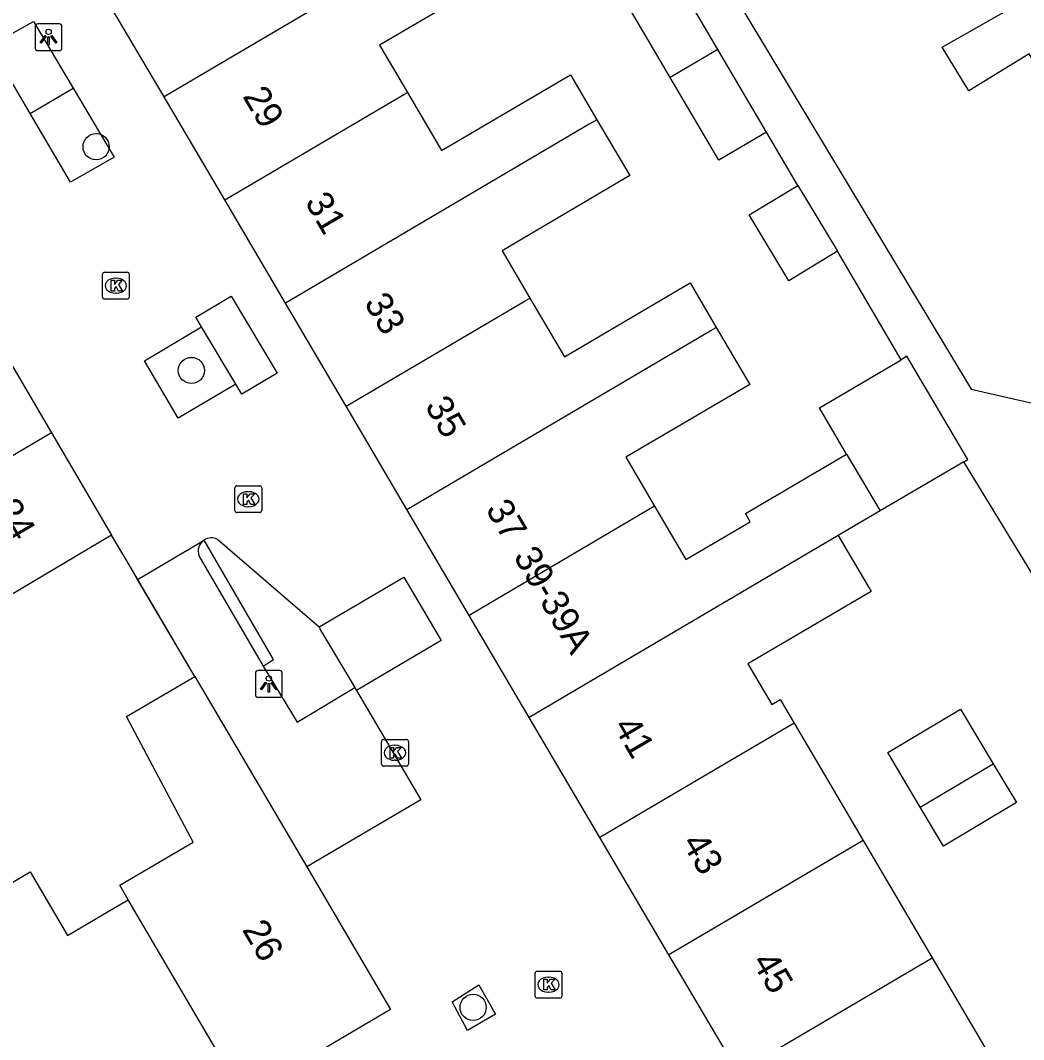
# Model space of a CAD drawing. Extents: x 161771 to 163125, y 382479 to 383177.
# Drawn here: x 162197.24 to 162234.66, y 382820.33 to 382858.34 of the extents above; entities that cross this region are included whole.
import ezdxf

# ---------------------------------------------------------------- set-up
doc = ezdxf.new("R2010")
doc.units = 0
for name, color, linetype in [('IMGEO_Boom', 7, 'Continuous'), ('IMGEO_Groenvoorziening', 7, 'Continuous'), ('IMGEO_Kolk', 7, 'Continuous'), ('IMGEO_Lichtpunt', 7, 'Continuous'), ('IMGEO_Muur', 7, 'Continuous'), ('IMGEO_Pand', 7, 'Continuous'), ('IMGEO_Pand_nummerreeks', 7, 'Continuous'), ('IMGEO_Parkeervlak_open', 7, 'Continuous'), ('IMGEO_Voetpad_open', 7, 'Continuous'), ('IMGEO_Woonerf_open', 7, 'Continuous')]:
    doc.layers.add(name, color=color, linetype=linetype)

msp = doc.modelspace()

# ---------------------------------------------------------------- linework, layer by layer
at = {"layer": 'IMGEO_Boom'}
for centre in [(162200.067, 382853.624), (162203.62, 382845.282), (162214.13, 382821.532)]:
    msp.add_circle(centre, 0.489, dxfattribs=at)
at = {"layer": 'IMGEO_Groenvoorziening'}
msp.add_lwpolyline([(162197.603, 382854.86), (162199.207, 382855.812)], dxfattribs=at)
at = {"layer": 'IMGEO_Kolk'}
for p, q in [((162200.304, 382848.017), (162200.304, 382848.869)), ((162200.379, 382848.943), (162201.231, 382848.943)), ((162200.792, 382848.723), (162200.817, 382848.723)), ((162201.305, 382848.869), (162201.305, 382848.017)), ((162201.231, 382847.943), (162200.379, 382847.943)), ((162200.815, 382848.163), (162200.79, 382848.163)), ((162205.243, 382840.056), (162205.243, 382840.908)), ((162205.318, 382840.982), (162206.17, 382840.982)), ((162205.731, 382840.762), (162205.756, 382840.762)), ((162206.244, 382840.908), (162206.244, 382840.056)), ((162206.17, 382839.982), (162205.318, 382839.982)), ((162205.754, 382840.202), (162205.729, 382840.202)), ((162210.714, 382830.598), (162210.714, 382831.45)), ((162210.789, 382831.524), (162211.641, 382831.524)), ((162211.202, 382831.304), (162211.227, 382831.304)), ((162211.715, 382831.45), (162211.715, 382830.598)), ((162211.641, 382830.524), (162210.789, 382830.524)), ((162211.225, 382830.744), (162211.2, 382830.744)), ((162216.442, 382821.953), (162216.442, 382822.805)), ((162216.517, 382822.879), (162217.369, 382822.879)), ((162217.443, 382822.805), (162217.443, 382821.953)), ((162216.93, 382822.659), (162216.955, 382822.659)), ((162216.953, 382822.099), (162216.928, 382822.099)), ((162217.369, 382821.879), (162216.517, 382821.879))]:
    msp.add_line(p, q, dxfattribs=at)
for points in [[(162200.304, 382848.017), (162200.304, 382848.869)], [(162200.379, 382848.943), (162201.231, 382848.943)], [(162201.305, 382848.869), (162201.305, 382848.017)], [(162200.625, 382848.643), (162200.748, 382848.643), (162200.748, 382848.492), (162200.878, 382848.643), (162201.042, 382848.643), (162200.896, 382848.492), (162201.049, 382848.243), (162200.897, 382848.243), (162200.812, 382848.407), (162200.748, 382848.34), (162200.748, 382848.243), (162200.625, 382848.243), (162200.625, 382848.643)], [(162201.231, 382847.943), (162200.379, 382847.943)], [(162205.243, 382840.056), (162205.243, 382840.908)], [(162205.318, 382840.982), (162206.17, 382840.982)], [(162205.564, 382840.682), (162205.687, 382840.682), (162205.687, 382840.531), (162205.817, 382840.682), (162205.981, 382840.682), (162205.835, 382840.531), (162205.988, 382840.282), (162205.836, 382840.282), (162205.751, 382840.446), (162205.687, 382840.379), (162205.687, 382840.282), (162205.564, 382840.282), (162205.564, 382840.682)], [(162206.244, 382840.908), (162206.244, 382840.056)], [(162206.17, 382839.982), (162205.318, 382839.982)], [(162210.714, 382830.598), (162210.714, 382831.45)], [(162210.789, 382831.524), (162211.641, 382831.524)], [(162211.035, 382831.224), (162211.158, 382831.224), (162211.158, 382831.073), (162211.288, 382831.224), (162211.452, 382831.224), (162211.306, 382831.073), (162211.459, 382830.824), (162211.307, 382830.824), (162211.222, 382830.988), (162211.158, 382830.921), (162211.158, 382830.824), (162211.035, 382830.824), (162211.035, 382831.224)], [(162211.715, 382831.45), (162211.715, 382830.598)], [(162211.641, 382830.524), (162210.789, 382830.524)], [(162216.442, 382821.953), (162216.442, 382822.805)], [(162216.517, 382822.879), (162217.369, 382822.879)], [(162217.443, 382822.805), (162217.443, 382821.953)], [(162216.763, 382822.579), (162216.886, 382822.579), (162216.886, 382822.428), (162217.016, 382822.579), (162217.18, 382822.579), (162217.034, 382822.428), (162217.187, 382822.179), (162217.035, 382822.179), (162216.95, 382822.343), (162216.886, 382822.276), (162216.886, 382822.179), (162216.763, 382822.179), (162216.763, 382822.579)], [(162217.369, 382821.879), (162216.517, 382821.879)]]:
    msp.add_lwpolyline(points, dxfattribs=at)
for centre, start, end in [((162200.381, 382848.867), 91.552, 178.448), ((162200.381, 382848.867), 91.552, 178.448), ((162201.229, 382848.867), 1.552, 88.448), ((162201.229, 382848.867), 1.552, 88.448), ((162200.381, 382848.019), 181.552, 268.448), ((162200.381, 382848.019), 181.552, 268.448), ((162201.229, 382848.019), 271.552, 358.448), ((162201.229, 382848.019), 271.552, 358.448), ((162205.32, 382840.906), 91.552, 178.448), ((162205.32, 382840.906), 91.552, 178.448), ((162206.168, 382840.906), 1.552, 88.448), ((162206.168, 382840.906), 1.552, 88.448), ((162205.32, 382840.058), 181.552, 268.448), ((162205.32, 382840.058), 181.552, 268.448), ((162206.168, 382840.058), 271.552, 358.448), ((162206.168, 382840.058), 271.552, 358.448), ((162210.791, 382831.448), 91.552, 178.448), ((162210.791, 382831.448), 91.552, 178.448), ((162211.639, 382831.448), 1.552, 88.448), ((162211.639, 382831.448), 1.552, 88.448), ((162210.791, 382830.6), 181.552, 268.448), ((162210.791, 382830.6), 181.552, 268.448), ((162211.639, 382830.6), 271.552, 358.448), ((162211.639, 382830.6), 271.552, 358.448), ((162216.519, 382822.803), 91.552, 178.448), ((162216.519, 382822.803), 91.552, 178.448), ((162217.367, 382822.803), 1.552, 88.448), ((162217.367, 382822.803), 1.552, 88.448), ((162216.519, 382821.955), 181.552, 268.448), ((162216.519, 382821.955), 181.552, 268.448), ((162217.367, 382821.955), 271.552, 358.448), ((162217.367, 382821.955), 271.552, 358.448)]:
    msp.add_arc(centre, 0.0765, start, end, dxfattribs=at)
for centre, major_axis, ratio, start_param, end_param in [((162200.791, 382848.443), (-0.387, 0.002), 0.722429, 4.712389, 7.853982), ((162200.816, 382848.443), (-0.39, 0.002), 0.717154, 1.570796, 4.712389), ((162205.73, 382840.482), (-0.387, 0.002), 0.722429, 4.712389, 7.853982), ((162205.755, 382840.482), (-0.39, 0.002), 0.717154, 1.570796, 4.712389), ((162211.201, 382831.024), (-0.387, 0.002), 0.722429, 4.712389, 7.853982), ((162211.226, 382831.024), (-0.39, 0.002), 0.717154, 1.570796, 4.712389), ((162216.929, 382822.379), (-0.387, 0.002), 0.722429, 4.712389, 7.853982), ((162216.954, 382822.379), (-0.39, 0.002), 0.717154, 1.570796, 4.712389)]:
    msp.add_ellipse(centre, major_axis=major_axis, ratio=ratio, start_param=start_param, end_param=end_param, dxfattribs=at)
at = {"layer": 'IMGEO_Lichtpunt'}
for p, q in [((162198.698, 382858.207), (162197.89, 382858.207)), ((162198.698, 382858.207), (162197.89, 382858.207)), ((162197.796, 382858.112), (162197.796, 382857.305)), ((162197.796, 382858.112), (162197.796, 382857.305)), ((162198.792, 382857.305), (162198.792, 382858.112)), ((162198.792, 382857.305), (162198.792, 382858.112)), ((162197.89, 382857.211), (162198.698, 382857.211)), ((162197.89, 382857.211), (162198.698, 382857.211)), ((162206.011, 382833.997), (162206.011, 382833.19)), ((162206.011, 382833.997), (162206.011, 382833.19)), ((162206.913, 382834.092), (162206.105, 382834.092)), ((162206.913, 382834.092), (162206.105, 382834.092)), ((162207.007, 382833.19), (162207.007, 382833.997)), ((162207.007, 382833.19), (162207.007, 382833.997)), ((162206.105, 382833.096), (162206.913, 382833.096)), ((162206.105, 382833.096), (162206.913, 382833.096))]:
    msp.add_line(p, q, dxfattribs=at)
for points in [[(162198.17, 382857.776), (162198.209, 382857.748), (162198.021, 382857.486), (162197.983, 382857.513), (162198.17, 382857.776)], [(162198.382, 382857.748), (162198.42, 382857.775), (162198.607, 382857.513), (162198.568, 382857.485), (162198.382, 382857.748)], [(162198.272, 382857.728), (162198.319, 382857.728), (162198.319, 382857.406), (162198.272, 382857.406), (162198.272, 382857.728)], [(162206.385, 382833.661), (162206.424, 382833.633), (162206.236, 382833.371), (162206.198, 382833.398), (162206.385, 382833.661)], [(162206.487, 382833.613), (162206.534, 382833.613), (162206.534, 382833.291), (162206.487, 382833.291), (162206.487, 382833.613)], [(162206.597, 382833.633), (162206.635, 382833.66), (162206.822, 382833.398), (162206.783, 382833.37), (162206.597, 382833.633)]]:
    msp.add_lwpolyline(points, dxfattribs=at)
for centre in [(162198.295, 382857.91), (162206.51, 382833.795)]:
    msp.add_circle(centre, 0.0994, dxfattribs=at)
for centre, start, end in [((162197.89, 382858.112), 90, 180), ((162197.89, 382858.112), 90, 180), ((162198.698, 382858.112), 0, 90), ((162198.698, 382858.112), 0, 90), ((162197.89, 382857.305), 180, 270), ((162197.89, 382857.305), 180, 270), ((162198.698, 382857.305), 270, 0), ((162198.698, 382857.305), 270, 360), ((162206.105, 382833.997), 90, 180), ((162206.105, 382833.997), 90, 180), ((162206.913, 382833.997), 0, 90), ((162206.913, 382833.997), 0, 90), ((162206.105, 382833.19), 180, 270), ((162206.105, 382833.19), 180, 270), ((162206.913, 382833.19), 270, 0), ((162206.913, 382833.19), 270, 360)]:
    msp.add_arc(centre, 0.0946, start, end, dxfattribs=at)
at = {"layer": 'IMGEO_Muur'}
msp.add_lwpolyline([(162203.743, 382833.873), (162201.172, 382838.24)], dxfattribs=at)
at = {"layer": 'IMGEO_Pand'}
for points in [[(162237.48, 382857.838), (162235.233, 382856.474), (162234.864, 382857.089), (162232.625, 382855.706), (162231.624, 382857.338), (162233.93, 382858.644), (162231.966, 382861.913), (162229.224, 382866.48)], [(162214.218, 382862.326), (162213.938, 382862.161), (162202.6, 382855.486)], [(162214.218, 382862.326), (162215.445, 382860.238), (162210.639, 382857.413), (162211.676, 382855.649)], [(162221.48, 382856.206), (162219.735, 382859.174), (162221.515, 382860.221)], [(162223.26, 382857.253), (162221.515, 382860.221)], [(162202.6, 382855.486), (162200.335, 382859.333)], [(162223.26, 382857.253), (162221.48, 382856.206)], [(162225.075, 382854.166), (162223.26, 382857.253)], [(162211.676, 382855.649), (162212.953, 382853.478), (162217.762, 382856.305), (162218.747, 382854.63)], [(162225.075, 382854.166), (162223.295, 382853.12), (162221.48, 382856.206)], [(162204.864, 382851.639), (162211.543, 382855.571), (162211.676, 382855.649)], [(162204.864, 382851.639), (162202.6, 382855.486)], [(162218.747, 382854.63), (162218.461, 382854.462), (162207.129, 382847.791)], [(162218.747, 382854.63), (162219.971, 382852.547), (162215.21, 382849.748), (162216.249, 382847.98)], [(162227.722, 382849.728), (162225.901, 382848.63), (162224.421, 382851.086), (162226.242, 382852.183)], [(162226.242, 382852.183), (162227.722, 382849.728)], [(162207.129, 382847.791), (162204.864, 382851.639)], [(162216.249, 382847.98), (162217.535, 382845.793), (162222.22, 382848.547), (162223.195, 382846.888)], [(162209.393, 382843.944), (162216.069, 382847.874), (162216.249, 382847.98)], [(162209.393, 382843.944), (162207.129, 382847.791)], [(162196.128, 382846.817), (162198.399, 382842.955)], [(162211.658, 382840.097), (162222.976, 382846.759), (162223.195, 382846.888)], [(162223.195, 382846.888), (162224.445, 382844.761), (162219.824, 382842.045), (162220.899, 382840.216)], [(162228.06, 382842.164), (162227.044, 382843.892), (162230.09, 382845.683)], [(162232.428, 382841.879), (162232.576, 382841.966), (162230.312, 382845.814), (162230.09, 382845.683)], [(162211.658, 382840.097), (162209.393, 382843.944)], [(162198.399, 382842.955), (162186.857, 382836.148), (162186.673, 382836.04)], [(162198.399, 382842.955), (162200.639, 382839.145)], [(162220.899, 382840.216), (162222.065, 382838.233), (162224.464, 382839.643), (162224.286, 382839.946), (162228.06, 382842.164)], [(162228.06, 382842.164), (162229.308, 382840.042)], [(162232.428, 382841.879), (162229.308, 382840.042)], [(162213.983, 382836.145), (162211.658, 382840.097)], [(162220.899, 382840.216), (162213.983, 382836.145)], [(162229.308, 382840.042), (162227.749, 382839.124)], [(162200.639, 382839.145), (162196.339, 382836.596), (162193.767, 382835.071), (162192.569, 382837.074), (162187.738, 382834.234), (162186.673, 382836.04)], [(162227.749, 382839.124), (162216.223, 382832.34)], [(162227.749, 382839.124), (162227.869, 382838.92), (162228.972, 382837.044), (162224.377, 382834.343), (162225.271, 382832.823), (162225.586, 382833.009), (162226.104, 382832.128)], [(162216.223, 382832.34), (162213.983, 382836.145)], [(162201.263, 382825.545), (162200.946, 382826.084), (162203.682, 382827.694), (162201.205, 382832.379), (162203.743, 382833.873)], [(162203.743, 382833.873), (162207.923, 382826.769)], [(162218.859, 382827.862), (162216.223, 382832.34)], [(162230.803, 382829.003), (162229.593, 382831.031), (162232.312, 382832.653), (162233.531, 382830.609)], [(162226.104, 382832.128), (162218.859, 382827.862)], [(162226.104, 382832.128), (162228.677, 382827.751)], [(162233.531, 382830.609), (162234.391, 382829.166), (162231.672, 382827.545), (162230.803, 382829.003)], [(162230.803, 382829.003), (162233.531, 382830.609)], [(162221.434, 382823.487), (162218.859, 382827.862)], [(162228.677, 382827.751), (162221.434, 382823.487)], [(162228.677, 382827.751), (162231.249, 382823.375)], [(162207.923, 382826.769), (162211.052, 382821.45), (162205.566, 382818.22)], [(162200.429, 382815.195), (162197.177, 382818.993), (162194.176, 382822.44), (162193.668, 382822.141), (162192.394, 382824.304), (162195.652, 382826.221), (162195.997, 382825.636), (162197.608, 382826.584), (162199.003, 382824.215), (162200.789, 382825.266), (162201.263, 382825.545)], [(162205.566, 382818.22), (162201.263, 382825.545)], [(162224.009, 382819.113), (162221.434, 382823.487)], [(162224.009, 382819.113), (162231.249, 382823.375)], [(162231.249, 382823.375), (162233.822, 382818.999), (162233.619, 382818.879)]]:
    msp.add_lwpolyline(points, dxfattribs=at)
at = {"layer": 'IMGEO_Parkeervlak_open'}
for points in [[(162204, 382846.907), (162203.786, 382847.265), (162205.101, 382848.051), (162206.815, 382845.184), (162205.5, 382844.398), (162205.275, 382844.774)], [(162205.275, 382844.774), (162204, 382846.907)], [(162201.613, 382837.491), (162204.092, 382838.951)], [(162203.743, 382833.873), (162201.613, 382837.491)], [(162206.304, 382834.255), (162207.57, 382832.165), (162209.715, 382833.454)], [(162209.715, 382833.454), (162209.776, 382833.35)], [(162209.776, 382833.35), (162212.176, 382829.271), (162207.923, 382826.769)]]:
    msp.add_lwpolyline(points, dxfattribs=at)
at = {"layer": 'IMGEO_Voetpad_open'}
for points in [[(162223.532, 382859.838), (162232.709, 382844.583), (162236.844, 382843.635), (162251.231, 382852.307), (162253.694, 382853.771)], [(162226.242, 382852.183), (162225.075, 382854.166)], [(162230.09, 382845.683), (162227.722, 382849.728)], [(162238.913, 382831.272), (162232.428, 382841.879)], [(162206.304, 382834.255), (162206.679, 382834.499), (162204.092, 382838.951)], [(162203.902, 382838.371), (162206.304, 382834.255)]]:
    msp.add_lwpolyline(points, dxfattribs=at)
msp.add_arc((162204.373, 382838.538), 0.5, 124.2093, 199.5145, dxfattribs=at)
at = {"layer": 'IMGEO_Woonerf_open'}
for points in [[(162197.603, 382854.86), (162196.11, 382857.398), (162197.735, 382858.29), (162199.207, 382855.812)], [(162199.207, 382855.812), (162200.74, 382853.233), (162199.107, 382852.304), (162197.603, 382854.86)], [(162205.275, 382844.774), (162203.133, 382843.508), (162201.866, 382845.645), (162204, 382846.907)], [(162201.613, 382837.491), (162201.172, 382838.24), (162200.639, 382839.145)], [(162204.608, 382838.979), (162208.381, 382835.72)], [(162208.381, 382835.72), (162211.54, 382837.579), (162212.935, 382835.209), (162209.776, 382833.35)], [(162208.381, 382835.72), (162208.432, 382835.597), (162209.715, 382833.454)], [(162214.344, 382822.374), (162214.965, 382821.274), (162213.92, 382820.672), (162213.344, 382821.739), (162214.344, 382822.374)]]:
    msp.add_lwpolyline(points, dxfattribs=at)
msp.add_arc((162204.373, 382838.539), 0.499, 61.9183, 124.2937, dxfattribs=at)

# ---------------------------------------------------------------- texts
at = {"layer": 'IMGEO_Pand_nummerreeks'}
for s, rotation, p in [('29', 300.4803, (162205.51, 382855.509)), ('31', 300.4803, (162207.833, 382851.561)), ('33', 300.4803, (162210.043, 382847.808)), ('35', 300.4803, (162212.309, 382843.957)), ('24', 300.4544, (162196.25, 382840.137)), ('37', 300.4803, (162214.576, 382840.106)), ('39-39A', 300.4869, (162215.612, 382838.346)), ('41', 300.4811, (162219.339, 382832.015)), ('43', 300.4803, (162221.894, 382827.672)), ('26', 300.4697, (162205.493, 382824.429)), ('45', 300.4803, (162224.506, 382823.234))]:
    msp.add_text(s, height=1, rotation=rotation, dxfattribs=at).set_placement(p)

doc.saveas('drawing.dxf')
